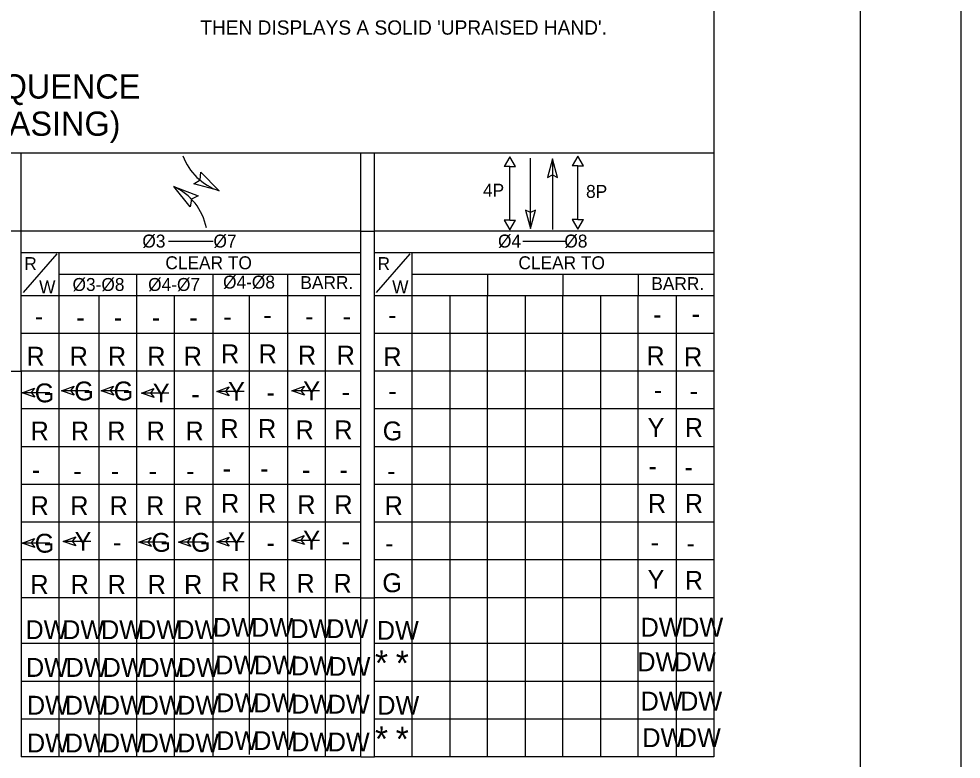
# Model space of a CAD drawing. Extents: x 0 to 3.01, y -0.05 to 1.83.
# Drawn here: x 2.6475 to 3, y 1.2626 to 1.5395 of the extents above; entities that cross this region are included whole.
import ezdxf

# ---------------------------------------------------------------- set-up
doc = ezdxf.new("R2010")
doc.units = 0
for name, color, linetype in [('RD_SHT_IplotShp', 7, 'Continuous'), ('TR_TS_Border', 7, 'Continuous'), ('TR_TS_Phase1', 7, 'Continuous'), ('TR_TS_Phase2', 7, 'Continuous'), ('TR_TS_Phase3', 7, 'Continuous'), ('TR_TS_Phase4', 7, 'Continuous'), ('TR_TS_Phase5', 7, 'Continuous'), ('TR_TS_Phase6', 7, 'Continuous'), ('TR_TS_Phase7', 7, 'Continuous'), ('TR_TS_Phase8', 7, 'Continuous')]:
    doc.layers.add(name, color=color, linetype=linetype)

msp = doc.modelspace()

# ---------------------------------------------------------------- linework, layer by layer
at = {"layer": 'RD_SHT_IplotShp'}
msp.add_lwpolyline([(-2.251068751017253e-08, -2.817312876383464e-08), (3.0000009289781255, -2.817312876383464e-08), (3.0000009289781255, 1.833330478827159), (-2.251068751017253e-08, 1.833330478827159)], close=True, dxfattribs=at)
at = {"layer": 'TR_TS_Border'}
for p, q in [((3.0000009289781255, -2.817312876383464e-08), (3.0000009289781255, 1.833330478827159)), ((2.9623453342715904, 0.04746639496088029), (2.9623453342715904, 1.7753952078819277)), ((2.907475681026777, 1.6927997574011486), (2.907475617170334, 1.2634423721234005)), ((2.9074756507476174, 1.4891940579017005), (2.2983729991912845, 1.4891940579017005)), ((2.6483222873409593, 1.4077126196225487), (2.6483222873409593, 1.4891941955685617)), ((2.7753416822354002, 1.4891941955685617), (2.7753416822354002, 1.2634424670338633)), ((2.7804035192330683, 1.4891941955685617), (2.7804035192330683, 1.2634424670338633)), ((2.6483222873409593, 1.4601230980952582), (2.638251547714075, 1.4601230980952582)), ((2.7753416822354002, 1.4601230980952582), (2.6483222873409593, 1.4601230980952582)), ((2.7753416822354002, 1.4601230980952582), (2.7804035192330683, 1.4601230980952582)), ((2.9074755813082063, 1.4601230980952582), (2.7804035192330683, 1.4601230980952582)), ((2.70341308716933, 1.4563796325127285), (2.7201928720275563, 1.4563796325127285)), ((2.8360270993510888, 1.4563796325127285), (2.8521898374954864, 1.4563796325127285)), ((2.6483222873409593, 1.4520558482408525), (2.7753416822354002, 1.4520558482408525)), ((2.64916603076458, 1.4371341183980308), (2.661820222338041, 1.4515814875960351)), ((2.6624004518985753, 1.4520558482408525), (2.6624004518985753, 1.2634424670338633)), ((2.7804035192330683, 1.4520558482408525), (2.9074755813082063, 1.4520558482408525)), ((2.78124717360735, 1.4371341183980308), (2.79390145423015, 1.4515814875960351)), ((2.794534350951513, 1.4520558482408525), (2.794534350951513, 1.2634424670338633)), ((2.6624004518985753, 1.4439888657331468), (2.7753416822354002, 1.4439888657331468)), ((2.6915342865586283, 1.4439888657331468), (2.6915342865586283, 1.2634424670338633)), ((2.720036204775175, 1.4440881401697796), (2.720036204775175, 1.2635417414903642)), ((2.7479267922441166, 1.4439888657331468), (2.7479267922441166, 1.2638396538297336)), ((2.794534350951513, 1.4439888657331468), (2.9074755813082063, 1.4439888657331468)), ((2.8227432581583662, 1.4439888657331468), (2.8227432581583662, 1.4359214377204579)), ((2.8510049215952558, 1.4439888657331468), (2.8510049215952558, 1.4359214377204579)), ((2.8792141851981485, 1.4439888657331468), (2.8792141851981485, 1.4359214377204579)), ((2.7753416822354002, 1.4359214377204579), (2.6483222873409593, 1.4359214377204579)), ((2.677403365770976, 1.4359214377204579), (2.677403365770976, 1.2634424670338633)), ((2.705612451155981, 1.4359214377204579), (2.705612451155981, 1.2634424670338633)), ((2.7336919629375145, 1.4359214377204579), (2.7336919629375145, 1.2643360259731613)), ((2.7620573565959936, 1.4359214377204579), (2.7620573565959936, 1.2638396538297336)), ((2.9074755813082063, 1.4359214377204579), (2.7804035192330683, 1.4359214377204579)), ((2.808665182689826, 1.4359214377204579), (2.808665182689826, 1.2634424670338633)), ((2.8227432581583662, 1.2634424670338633), (2.8227432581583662, 1.4359214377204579)), ((2.8368740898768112, 1.4359214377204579), (2.8368740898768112, 1.2634424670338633)), ((2.8510049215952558, 1.2634424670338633), (2.8510049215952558, 1.4359214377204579)), ((2.8651358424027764, 1.4359214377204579), (2.8651358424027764, 1.2634424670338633)), ((2.8792141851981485, 1.2634424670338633), (2.8792141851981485, 1.4359214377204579)), ((2.8933446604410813, 1.4359214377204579), (2.8933446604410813, 1.2634424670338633)), ((2.7753416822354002, 1.4217904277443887), (2.6483222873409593, 1.4217904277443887)), ((2.9074755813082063, 1.4217904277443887), (2.7804035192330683, 1.4217904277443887)), ((2.638251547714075, 1.4077126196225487), (2.6483222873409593, 1.4077126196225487)), ((2.7753416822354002, 1.4077126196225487), (2.6483222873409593, 1.4077126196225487)), ((2.6483222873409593, 1.4077126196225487), (2.6483222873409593, 1.2634424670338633)), ((2.9074755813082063, 1.4077126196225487), (2.7804035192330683, 1.4077126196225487)), ((2.7753416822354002, 1.39358169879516), (2.6483222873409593, 1.39358169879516)), ((2.9074755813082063, 1.39358169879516), (2.7804035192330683, 1.39358169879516)), ((2.7753416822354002, 1.3794506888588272), (2.6483222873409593, 1.3794506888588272)), ((2.9074755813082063, 1.3794506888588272), (2.7804035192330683, 1.3794506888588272)), ((2.7753416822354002, 1.365372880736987), (2.6483222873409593, 1.365372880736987)), ((2.9074755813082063, 1.365372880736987), (2.7804035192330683, 1.365372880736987)), ((2.7753416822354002, 1.3512419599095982), (2.6483222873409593, 1.3512419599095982)), ((2.9074755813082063, 1.3512419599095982), (2.7804035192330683, 1.3512419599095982)), ((2.7753416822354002, 1.3371109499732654), (2.6483222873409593, 1.3371109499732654)), ((2.9074755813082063, 1.3371109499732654), (2.7804035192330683, 1.3371109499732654)), ((2.7753416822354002, 1.3229801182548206), (2.6483222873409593, 1.3229801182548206)), ((2.7753416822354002, 1.3229801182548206), (2.7804035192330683, 1.3229801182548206)), ((2.9074755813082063, 1.3229801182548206), (2.7804035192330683, 1.3229801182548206)), ((2.775415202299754, 1.3058350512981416), (2.6483956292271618, 1.3058350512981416)), ((2.9075490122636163, 1.3058350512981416), (2.7804767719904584, 1.3058350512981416)), ((2.775415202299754, 1.2917041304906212), (2.6483956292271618, 1.2917041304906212)), ((2.9075490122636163, 1.2917041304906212), (2.7804767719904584, 1.2917041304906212)), ((2.775415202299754, 1.2775732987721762), (2.6483956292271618, 1.2775732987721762)), ((2.9075490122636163, 1.2775732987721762), (2.7804767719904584, 1.2775732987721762)), ((2.775415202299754, 1.2634424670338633), (2.6483956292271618, 1.2634424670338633)), ((2.775415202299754, 1.2634424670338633), (2.7804767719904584, 1.2634424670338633)), ((2.9074755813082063, 1.2634424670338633), (2.7804767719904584, 1.2634424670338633))]:
    msp.add_line(p, q, dxfattribs=at)
at = {"layer": 'TR_TS_Phase3'}
for p, q in [((2.7115723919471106, 1.4692163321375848), (2.7055207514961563, 1.4767562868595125)), ((2.7055207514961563, 1.4767562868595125), (2.7145458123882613, 1.4732342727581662)), ((2.7120208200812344, 1.471990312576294), (2.7115723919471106, 1.4692163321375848)), ((2.7145458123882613, 1.4732342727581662), (2.7120208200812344, 1.471990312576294)), ((2.64874799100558, 1.3996445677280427), (2.653382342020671, 1.4014073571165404)), ((2.6590093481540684, 1.3996445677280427), (2.64874799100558, 1.3996445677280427)), ((2.6534263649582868, 1.398036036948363), (2.64874799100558, 1.3996445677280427)), ((2.653382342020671, 1.4014073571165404), (2.6520530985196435, 1.399703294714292)), ((2.6520530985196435, 1.399703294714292), (2.6534263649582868, 1.398036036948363)), ((2.663497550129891, 1.4003606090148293), (2.6681319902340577, 1.4021232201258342)), ((2.6737589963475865, 1.4003606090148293), (2.663497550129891, 1.4003606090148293)), ((2.6681760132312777, 1.398752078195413), (2.663497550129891, 1.4003606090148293)), ((2.6681319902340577, 1.4021232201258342), (2.6668026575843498, 1.4004193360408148)), ((2.6668026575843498, 1.4004193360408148), (2.6681760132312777, 1.398752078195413)), ((2.678290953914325, 1.4003606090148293), (2.6829253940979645, 1.4021232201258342)), ((2.688552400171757, 1.4003606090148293), (2.678290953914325, 1.4003606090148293)), ((2.6829694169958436, 1.398752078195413), (2.678290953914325, 1.4003606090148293)), ((2.6829253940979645, 1.4021232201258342), (2.6815960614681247, 1.4004193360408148)), ((2.6815960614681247, 1.4004193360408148), (2.6829694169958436, 1.398752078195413)), ((2.6933698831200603, 1.399482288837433), (2.6980042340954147, 1.4012450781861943)), ((2.6980042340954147, 1.4012450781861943), (2.6966749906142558, 1.3995411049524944)), ((2.6966749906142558, 1.3995411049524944), (2.6980484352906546, 1.397873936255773)), ((2.7215224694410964, 1.400115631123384), (2.7261569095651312, 1.4018784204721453)), ((2.7317835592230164, 1.400115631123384), (2.7215224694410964, 1.400115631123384)), ((2.726200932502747, 1.3985071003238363), (2.7215224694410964, 1.400115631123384)), ((2.7261569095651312, 1.4018784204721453), (2.7248275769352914, 1.4001743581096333)), ((2.7248275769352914, 1.4001743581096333), (2.726200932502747, 1.3985071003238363)), ((2.7496468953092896, 1.4003026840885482), (2.7542813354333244, 1.402065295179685)), ((2.7599079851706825, 1.4003026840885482), (2.7496468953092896, 1.4003026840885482)), ((2.754325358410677, 1.3986941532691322), (2.7496468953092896, 1.4003026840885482)), ((2.7542813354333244, 1.402065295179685), (2.7529520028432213, 1.4003614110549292)), ((2.7529520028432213, 1.4003614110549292), (2.754325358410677, 1.3986941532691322)), ((2.7036308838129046, 1.399482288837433), (2.6933698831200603, 1.399482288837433)), ((2.6980484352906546, 1.397873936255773), (2.6933698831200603, 1.399482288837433))]:
    msp.add_line(p, q, dxfattribs=at)
msp.add_arc((2.696452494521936, 1.4570710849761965), 0.021617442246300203, 11.426533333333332, 65.38743333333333, dxfattribs=at)
at = {"layer": 'TR_TS_Phase4'}
for p, q in [((2.83115707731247, 1.4879070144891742), (2.8290249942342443, 1.4842348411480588)), ((2.8332894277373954, 1.4842348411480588), (2.83115707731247, 1.4879070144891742)), ((2.83115707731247, 1.4842348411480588), (2.8290249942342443, 1.4842348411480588)), ((2.83115707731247, 1.4642685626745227), (2.83115707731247, 1.4842348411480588)), ((2.83115707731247, 1.4842348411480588), (2.8332894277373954, 1.4842348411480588)), ((2.838885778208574, 1.4610221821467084), (2.838885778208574, 1.4874079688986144)), ((2.838885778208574, 1.4669921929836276), (2.8370200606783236, 1.4679516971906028)), ((2.8370200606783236, 1.4679516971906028), (2.838885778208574, 1.4610221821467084)), ((2.8407514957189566, 1.4679516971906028), (2.838885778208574, 1.4669921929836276)), ((2.838885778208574, 1.4610221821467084), (2.8407514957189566, 1.4679516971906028)), ((2.83115707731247, 1.4641970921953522), (2.82902481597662, 1.4641970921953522)), ((2.82902481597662, 1.4641970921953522), (2.83115707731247, 1.460524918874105)), ((2.83115707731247, 1.460524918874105), (2.8332892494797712, 1.4641970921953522)), ((2.83115707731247, 1.4641970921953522), (2.8332892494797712, 1.4641970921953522))]:
    msp.add_line(p, q, dxfattribs=at)
at = {"layer": 'TR_TS_Phase7'}
for p, q in [((2.7153590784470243, 1.4792849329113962), (2.7155031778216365, 1.4820912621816)), ((2.7155031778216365, 1.4820912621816), (2.722339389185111, 1.4752549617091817)), ((2.7129845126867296, 1.4777736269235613), (2.7153590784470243, 1.4792849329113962)), ((2.722339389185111, 1.4752549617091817), (2.7129845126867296, 1.4777736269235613)), ((2.64874799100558, 1.3434204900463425), (2.653382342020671, 1.3451831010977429)), ((2.6590093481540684, 1.3434204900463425), (2.64874799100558, 1.3434204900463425)), ((2.6534263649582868, 1.341811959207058), (2.64874799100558, 1.3434204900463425)), ((2.653382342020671, 1.3451831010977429), (2.6520530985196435, 1.3434792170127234)), ((2.6520530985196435, 1.3434792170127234), (2.6534263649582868, 1.341811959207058)), ((2.6641110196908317, 1.344039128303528), (2.668745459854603, 1.3458017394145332)), ((2.6743721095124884, 1.344039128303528), (2.6641110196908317, 1.344039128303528)), ((2.668789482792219, 1.34243059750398), (2.6641110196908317, 1.344039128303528)), ((2.668745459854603, 1.3458017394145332), (2.667416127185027, 1.344097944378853)), ((2.667416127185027, 1.344097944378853), (2.668789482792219, 1.34243059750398)), ((2.692366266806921, 1.34374584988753), (2.6970007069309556, 1.3455086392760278)), ((2.702627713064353, 1.34374584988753), (2.692366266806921, 1.34374584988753)), ((2.6970447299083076, 1.342137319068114), (2.692366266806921, 1.34374584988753)), ((2.6970007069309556, 1.3455086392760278), (2.6956713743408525, 1.3438046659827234)), ((2.6956713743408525, 1.3438046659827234), (2.6970447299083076, 1.342137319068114)), ((2.7071596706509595, 1.34374584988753), (2.7117941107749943, 1.3455086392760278)), ((2.7174209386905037, 1.34374584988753), (2.7071596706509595, 1.34374584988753)), ((2.71183813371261, 1.342137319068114), (2.7071596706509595, 1.34374584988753)), ((2.7117941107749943, 1.3455086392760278), (2.7104647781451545, 1.3438046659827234)), ((2.7104647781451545, 1.3438046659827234), (2.71183813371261, 1.342137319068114)), ((2.7215224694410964, 1.343891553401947), (2.7261569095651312, 1.3456541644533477)), ((2.7317835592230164, 1.343891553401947), (2.7215224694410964, 1.343891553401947)), ((2.726200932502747, 1.3422830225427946), (2.7215224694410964, 1.343891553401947)), ((2.7261569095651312, 1.3456541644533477), (2.7248275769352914, 1.34395028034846)), ((2.7248275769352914, 1.34395028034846), (2.726200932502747, 1.3422830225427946)), ((2.7496418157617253, 1.3444363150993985), (2.7542762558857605, 1.3461989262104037)), ((2.7599029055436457, 1.3444363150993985), (2.7496418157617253, 1.3444363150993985)), ((2.7543204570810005, 1.3428277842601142), (2.7496418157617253, 1.3444363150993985)), ((2.7542762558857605, 1.3461989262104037), (2.7529469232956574, 1.34449513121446)), ((2.7529469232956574, 1.34449513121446), (2.7543204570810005, 1.3428277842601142))]:
    msp.add_line(p, q, dxfattribs=at)
msp.add_arc((2.7291738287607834, 1.4957028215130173), 0.021617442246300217, 200.13881944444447, 251.63656666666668, dxfattribs=at)
at = {"layer": 'TR_TS_Phase8'}
for p, q in [((2.856626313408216, 1.4881698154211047), (2.8544943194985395, 1.4844975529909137)), ((2.8587587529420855, 1.4844975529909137), (2.856626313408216, 1.4881698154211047)), ((2.8471289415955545, 1.487125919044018), (2.8452631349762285, 1.4801964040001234)), ((2.8471289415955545, 1.487125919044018), (2.8471289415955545, 1.4607401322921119)), ((2.8489946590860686, 1.4801964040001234), (2.8471289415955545, 1.487125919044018)), ((2.856626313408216, 1.4844975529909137), (2.8544943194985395, 1.4844975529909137)), ((2.856626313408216, 1.4645311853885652), (2.856626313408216, 1.4844975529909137)), ((2.856626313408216, 1.4844975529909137), (2.8587587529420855, 1.4844975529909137)), ((2.8452631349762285, 1.4801964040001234), (2.8471289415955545, 1.4811559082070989)), ((2.8471289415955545, 1.4811559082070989), (2.8489946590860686, 1.4801964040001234)), ((2.856626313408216, 1.4644597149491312), (2.8544941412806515, 1.4644597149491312)), ((2.8544941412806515, 1.4644597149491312), (2.856626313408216, 1.4607875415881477)), ((2.856626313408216, 1.4607875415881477), (2.858758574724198, 1.4644597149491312)), ((2.856626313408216, 1.4644597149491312), (2.858758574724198, 1.4644597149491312))]:
    msp.add_line(p, q, dxfattribs=at)

# ---------------------------------------------------------------- texts
at = {"layer": 'TR_TS_Border'}
for s, height, p in [("THEN DISPLAYS A SOLID 'UPRAISED HAND'.", 0.0053469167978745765, (2.7153569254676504, 1.5335564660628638)), ('SIGNAL DISPLAY SEQUENCE', 0.00906283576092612, (2.522526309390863, 1.5096612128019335)), ('(PREFERENTIAL PHASING)', 0.00906283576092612, (2.527912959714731, 1.4957467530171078))]:
    msp.add_text(s, height=height, dxfattribs=at).set_placement(p)
for s, height, p in [('Ø3          Ø7', 0.0048400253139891, (2.6936815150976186, 1.4539533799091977)), ('Ø4         Ø8', 0.0048400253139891, (2.826738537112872, 1.4539533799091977)), ('R', 0.004840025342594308, (2.649520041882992, 1.445516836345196)), ('CLEAR TO', 0.004840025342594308, (2.7022907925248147, 1.445833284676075)), ('R', 0.004840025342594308, (2.78165420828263, 1.445516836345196)), ('CLEAR TO', 0.004840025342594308, (2.83437193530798, 1.445833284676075)), ('Ø3-Ø8', 0.004840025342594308, (2.6675664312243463, 1.4377132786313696)), ('Ø4-Ø7', 0.004840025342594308, (2.695845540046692, 1.4377132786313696)), ('Ø4-Ø8', 0.004840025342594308, (2.7238724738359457, 1.4386068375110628)), ('BARR.', 0.004840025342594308, (2.7528023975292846, 1.4384268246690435)), ('BARR.', 0.004840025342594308, (2.8840896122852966, 1.438029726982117)), ('W', 0.004840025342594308, (2.6550672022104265, 1.4368168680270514)), ('W', 0.004840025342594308, (2.787148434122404, 1.4368168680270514))]:
    msp.add_text(s, height=height, rotation=360, dxfattribs=at).set_placement(p)
at = {"layer": 'TR_TS_Phase1'}
for p in [(2.653481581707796, 1.4247234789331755), (2.7239757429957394, 1.4245940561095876), (2.73890499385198, 1.4252161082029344), (2.754588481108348, 1.4247196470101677), (2.7686226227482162, 1.4247196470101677), (2.7856267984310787, 1.4252593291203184), (2.8847424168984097, 1.4254363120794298), (2.899193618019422, 1.425662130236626), (2.6689969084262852, 1.4243225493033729), (2.6830311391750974, 1.4243225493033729), (2.697218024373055, 1.4243225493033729), (2.7112523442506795, 1.4243225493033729)]:
    msp.add_text('-', height=0.007050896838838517, dxfattribs=at).set_placement(p)
at = {"layer": 'TR_TS_Phase2'}
for s, p in [('R', (2.7231108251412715, 1.4106771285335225)), ('R', (2.7371882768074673, 1.4106771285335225)), ('R', (2.75186823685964, 1.4101806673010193)), ('R', (2.7663852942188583, 1.4101806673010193)), ('R', (2.6503331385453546, 1.4097835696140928)), ('R', (2.6664954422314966, 1.4097835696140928)), ('R', (2.6807927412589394, 1.4097835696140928)), ('R', (2.6955300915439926, 1.4097835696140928)), ('R', (2.709167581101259, 1.4097835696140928)), ('DW', (2.7200905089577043, 1.3083927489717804)), ('DW', (2.734387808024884, 1.3083927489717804)), ('DW', (2.749067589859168, 1.307896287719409)), ('DW', (2.7624849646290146, 1.307896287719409)), ('DW', (2.8800799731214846, 1.308428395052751)), ('DW', (2.8952674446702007, 1.308428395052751)), ('DW', (2.6499522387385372, 1.3074991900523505)), ('DW', (2.663694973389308, 1.3074991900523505)), ('DW', (2.6782122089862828, 1.3074991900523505)), ('DW', (2.6920696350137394, 1.3074991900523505)), ('DW', (2.706366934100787, 1.3074991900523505)), ('DW', (2.7813993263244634, 1.307240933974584))]:
    msp.add_text(s, height=0.007050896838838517, dxfattribs=at).set_placement(p)
for p in [(2.783834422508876, 1.409630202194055), (2.8822646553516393, 1.4099422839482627), (2.896344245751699, 1.4095685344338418)]:
    msp.add_text('R', height=0.007050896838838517, rotation=360, dxfattribs=at).set_placement(p)
at = {"layer": 'TR_TS_Phase3'}
for s, p in [('G', (2.6534249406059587, 1.396062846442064)), ('G', (2.668174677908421, 1.396778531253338)), ('G', (2.682968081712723, 1.396778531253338)), ('Y', (2.6975998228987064, 1.3959937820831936)), ('Y', (2.7257520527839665, 1.3966266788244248)), ('Y', (2.753876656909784, 1.396813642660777)), ('-', (2.7682469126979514, 1.396459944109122)), ('-', (2.7856806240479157, 1.3968304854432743)), ('-', (2.884997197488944, 1.3972142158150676)), ('-', (2.898418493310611, 1.3968304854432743)), ('-', (2.71197007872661, 1.3956399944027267)), ('-', (2.740122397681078, 1.39627298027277))]:
    msp.add_text(s, height=0.007050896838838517, dxfattribs=at).set_placement(p)
at = {"layer": 'TR_TS_Phase4'}
for s, height, p in [('4P', 0.004840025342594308, (2.821109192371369, 1.47295855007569)), ('R', 0.007050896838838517, (2.7228909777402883, 1.382727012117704)), ('R', 0.007050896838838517, (2.7369683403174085, 1.382727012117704)), ('R', 0.007050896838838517, (2.750988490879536, 1.382230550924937)), ('R', 0.007050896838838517, (2.7655057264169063, 1.382230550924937)), ('R', 0.007050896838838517, (2.6518727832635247, 1.381833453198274)), ('R', 0.007050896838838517, (2.666935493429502, 1.381833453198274)), ('R', 0.007050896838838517, (2.6805729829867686, 1.381833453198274)), ('R', 0.007050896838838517, (2.695310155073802, 1.381833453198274)), ('R', 0.007050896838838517, (2.70982739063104, 1.381833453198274)), ('DW', 0.007050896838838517, (2.7209329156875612, 1.2942764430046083)), ('DW', 0.007050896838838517, (2.73542929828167, 1.2942764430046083)), ('DW', 0.007050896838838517, (2.7493040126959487, 1.2939628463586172)), ('DW', 0.007050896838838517, (2.7633066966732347, 1.2937799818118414)), ('*', 0.009384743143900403, (2.78070302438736, 1.2938953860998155)), ('*', 0.009384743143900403, (2.7884735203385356, 1.2938389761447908)), ('DW', 0.007050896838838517, (2.8788573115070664, 1.2954670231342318)), ('DW', 0.007050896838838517, (2.8924870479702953, 1.2954670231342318)), ('DW', 0.007050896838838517, (2.650134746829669, 1.2933828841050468)), ('DW', 0.007050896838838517, (2.664956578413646, 1.2933828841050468)), ('DW', 0.007050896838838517, (2.6788140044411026, 1.2933828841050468)), ('DW', 0.007050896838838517, (2.6933310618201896, 1.2933828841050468)), ('DW', 0.007050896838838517, (2.7069685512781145, 1.2933828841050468))]:
    msp.add_text(s, height=height, dxfattribs=at).set_placement(p)
for s, p in [('G', (2.783613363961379, 1.3818451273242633)), ('Y', (2.8826877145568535, 1.3831205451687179)), ('R', (2.896606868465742, 1.3831205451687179))]:
    msp.add_text(s, height=0.007050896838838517, rotation=360, dxfattribs=at).set_placement(p)
at = {"layer": 'TR_TS_Phase5'}
for p in [(2.8830463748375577, 1.3687116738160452), (2.896467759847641, 1.3683280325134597), (2.6523114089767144, 1.3673283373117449), (2.667826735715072, 1.366927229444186), (2.6818609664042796, 1.366927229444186), (2.696047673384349, 1.366927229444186), (2.710081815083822, 1.366927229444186), (2.7237005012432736, 1.367820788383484), (2.7377348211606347, 1.367820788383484), (2.753418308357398, 1.3673243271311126), (2.7674524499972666, 1.3673243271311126), (2.785236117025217, 1.366936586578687)]:
    msp.add_text('-', height=0.007050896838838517, dxfattribs=at).set_placement(p)
at = {"layer": 'TR_TS_Phase6'}
for s, p in [('R', (2.6518727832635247, 1.353883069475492)), ('R', (2.6667153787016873, 1.353883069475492)), ('R', (2.681452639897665, 1.353883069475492)), ('R', (2.695090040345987, 1.353883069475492)), ('R', (2.709387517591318, 1.353883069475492)), ('R', (2.7231108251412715, 1.354776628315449)), ('R', (2.7369681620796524, 1.354776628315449)), ('R', (2.7516483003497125, 1.3542801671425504)), ('R', (2.7655057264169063, 1.3542801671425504)), ('DW', (2.721298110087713, 1.2801455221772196)), ('DW', (2.7351553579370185, 1.2801455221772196)), ('DW', (2.8800799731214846, 1.2807829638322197)), ('DW', (2.894877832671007, 1.2807829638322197)), ('DW', (2.650499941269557, 1.279251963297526)), ('DW', (2.664682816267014, 1.279251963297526)), ('DW', (2.6785400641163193, 1.279251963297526)), ('DW', (2.6930572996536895, 1.279251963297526)), ('DW', (2.7066947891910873, 1.279251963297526)), ('DW', (2.749395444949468, 1.2796490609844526)), ('DW', (2.763032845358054, 1.2796490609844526)), ('DW', (2.7815820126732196, 1.2792301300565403))]:
    msp.add_text(s, height=0.007050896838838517, dxfattribs=at).set_placement(p)
for p in [(2.7843186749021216, 1.3539110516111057), (2.8827897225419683, 1.354722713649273), (2.896606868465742, 1.354722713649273)]:
    msp.add_text('R', height=0.007050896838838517, rotation=360, dxfattribs=at).set_placement(p)
at = {"layer": 'TR_TS_Phase7'}
for s, p in [('G', (2.6534249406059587, 1.3398385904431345)), ('Y', (2.66834078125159, 1.3405505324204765)), ('G', (2.6970437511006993, 1.340164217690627)), ('G', (2.71183715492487, 1.340164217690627)), ('Y', (2.7257520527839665, 1.3404027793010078)), ('Y', (2.753871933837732, 1.3409476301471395)), ('-', (2.6827111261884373, 1.3401968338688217)), ('-', (2.740122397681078, 1.340049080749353)), ('-', (2.7682421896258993, 1.3405939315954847)), ('-', (2.883826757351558, 1.3402090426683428)), ('-', (2.7845100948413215, 1.3398254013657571)), ('-', (2.8972481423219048, 1.3398254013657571))]:
    msp.add_text(s, height=0.007050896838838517, dxfattribs=at).set_placement(p)
at = {"layer": 'TR_TS_Phase8'}
for s, height, p in [('8P', 0.004840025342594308, (2.859665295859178, 1.472506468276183)), ('R', 0.007050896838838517, (2.6517813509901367, 1.3244343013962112)), ('R', 0.007050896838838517, (2.6668439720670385, 1.3244343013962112)), ('R', 0.007050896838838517, (2.6807013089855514, 1.3244343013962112)), ('R', 0.007050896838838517, (2.695658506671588, 1.3244343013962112)), ('R', 0.007050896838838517, (2.7092959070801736, 1.3244343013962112)), ('R', 0.007050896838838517, (2.723239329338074, 1.3253278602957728)), ('R', 0.007050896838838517, (2.737096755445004, 1.3253278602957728)), ('R', 0.007050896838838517, (2.75133675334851, 1.3248313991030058)), ('R', 0.007050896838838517, (2.7651940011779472, 1.3248313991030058)), ('DW', 0.007050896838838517, (2.721298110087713, 1.2660146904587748)), ('DW', 0.007050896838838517, (2.7351553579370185, 1.2660146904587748)), ('*', 0.009384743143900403, (2.78070302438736, 1.265489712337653)), ('*', 0.009384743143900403, (2.7884735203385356, 1.265433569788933)), ('DW', 0.007050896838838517, (2.880742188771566, 1.2671042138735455)), ('DW', 0.007050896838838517, (2.8943718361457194, 1.2671042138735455)), ('DW', 0.007050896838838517, (2.650499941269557, 1.2651211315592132)), ('DW', 0.007050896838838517, (2.664682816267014, 1.2651211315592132)), ('DW', 0.007050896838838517, (2.6785400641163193, 1.2651211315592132)), ('DW', 0.007050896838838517, (2.6930572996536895, 1.2651211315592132)), ('DW', 0.007050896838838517, (2.7066947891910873, 1.2651211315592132)), ('DW', 0.007050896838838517, (2.749395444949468, 1.2655182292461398)), ('DW', 0.007050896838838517, (2.763032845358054, 1.2655182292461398))]:
    msp.add_text(s, height=height, dxfattribs=at).set_placement(p)
for s, p in [('Y', (2.8826877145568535, 1.3263247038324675)), ('R', (2.896606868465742, 1.3259510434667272)), ('G', (2.7834641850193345, 1.3250459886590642))]:
    msp.add_text(s, height=0.007050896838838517, rotation=360, dxfattribs=at).set_placement(p)

doc.saveas('drawing.dxf')
